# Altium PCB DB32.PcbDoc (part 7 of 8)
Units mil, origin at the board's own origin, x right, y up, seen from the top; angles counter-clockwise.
Board outline 3236.22 x 4456.69 mil, 8 copper layers (Top Layer, MidLayer1, MidLayer2, GND-Layer5, MidLayer3, VCC, MidLayer4, Bottom Layer), stack 61.8 mil thick; 207 components, 474 nets, 1777 pads, 1474 vias.
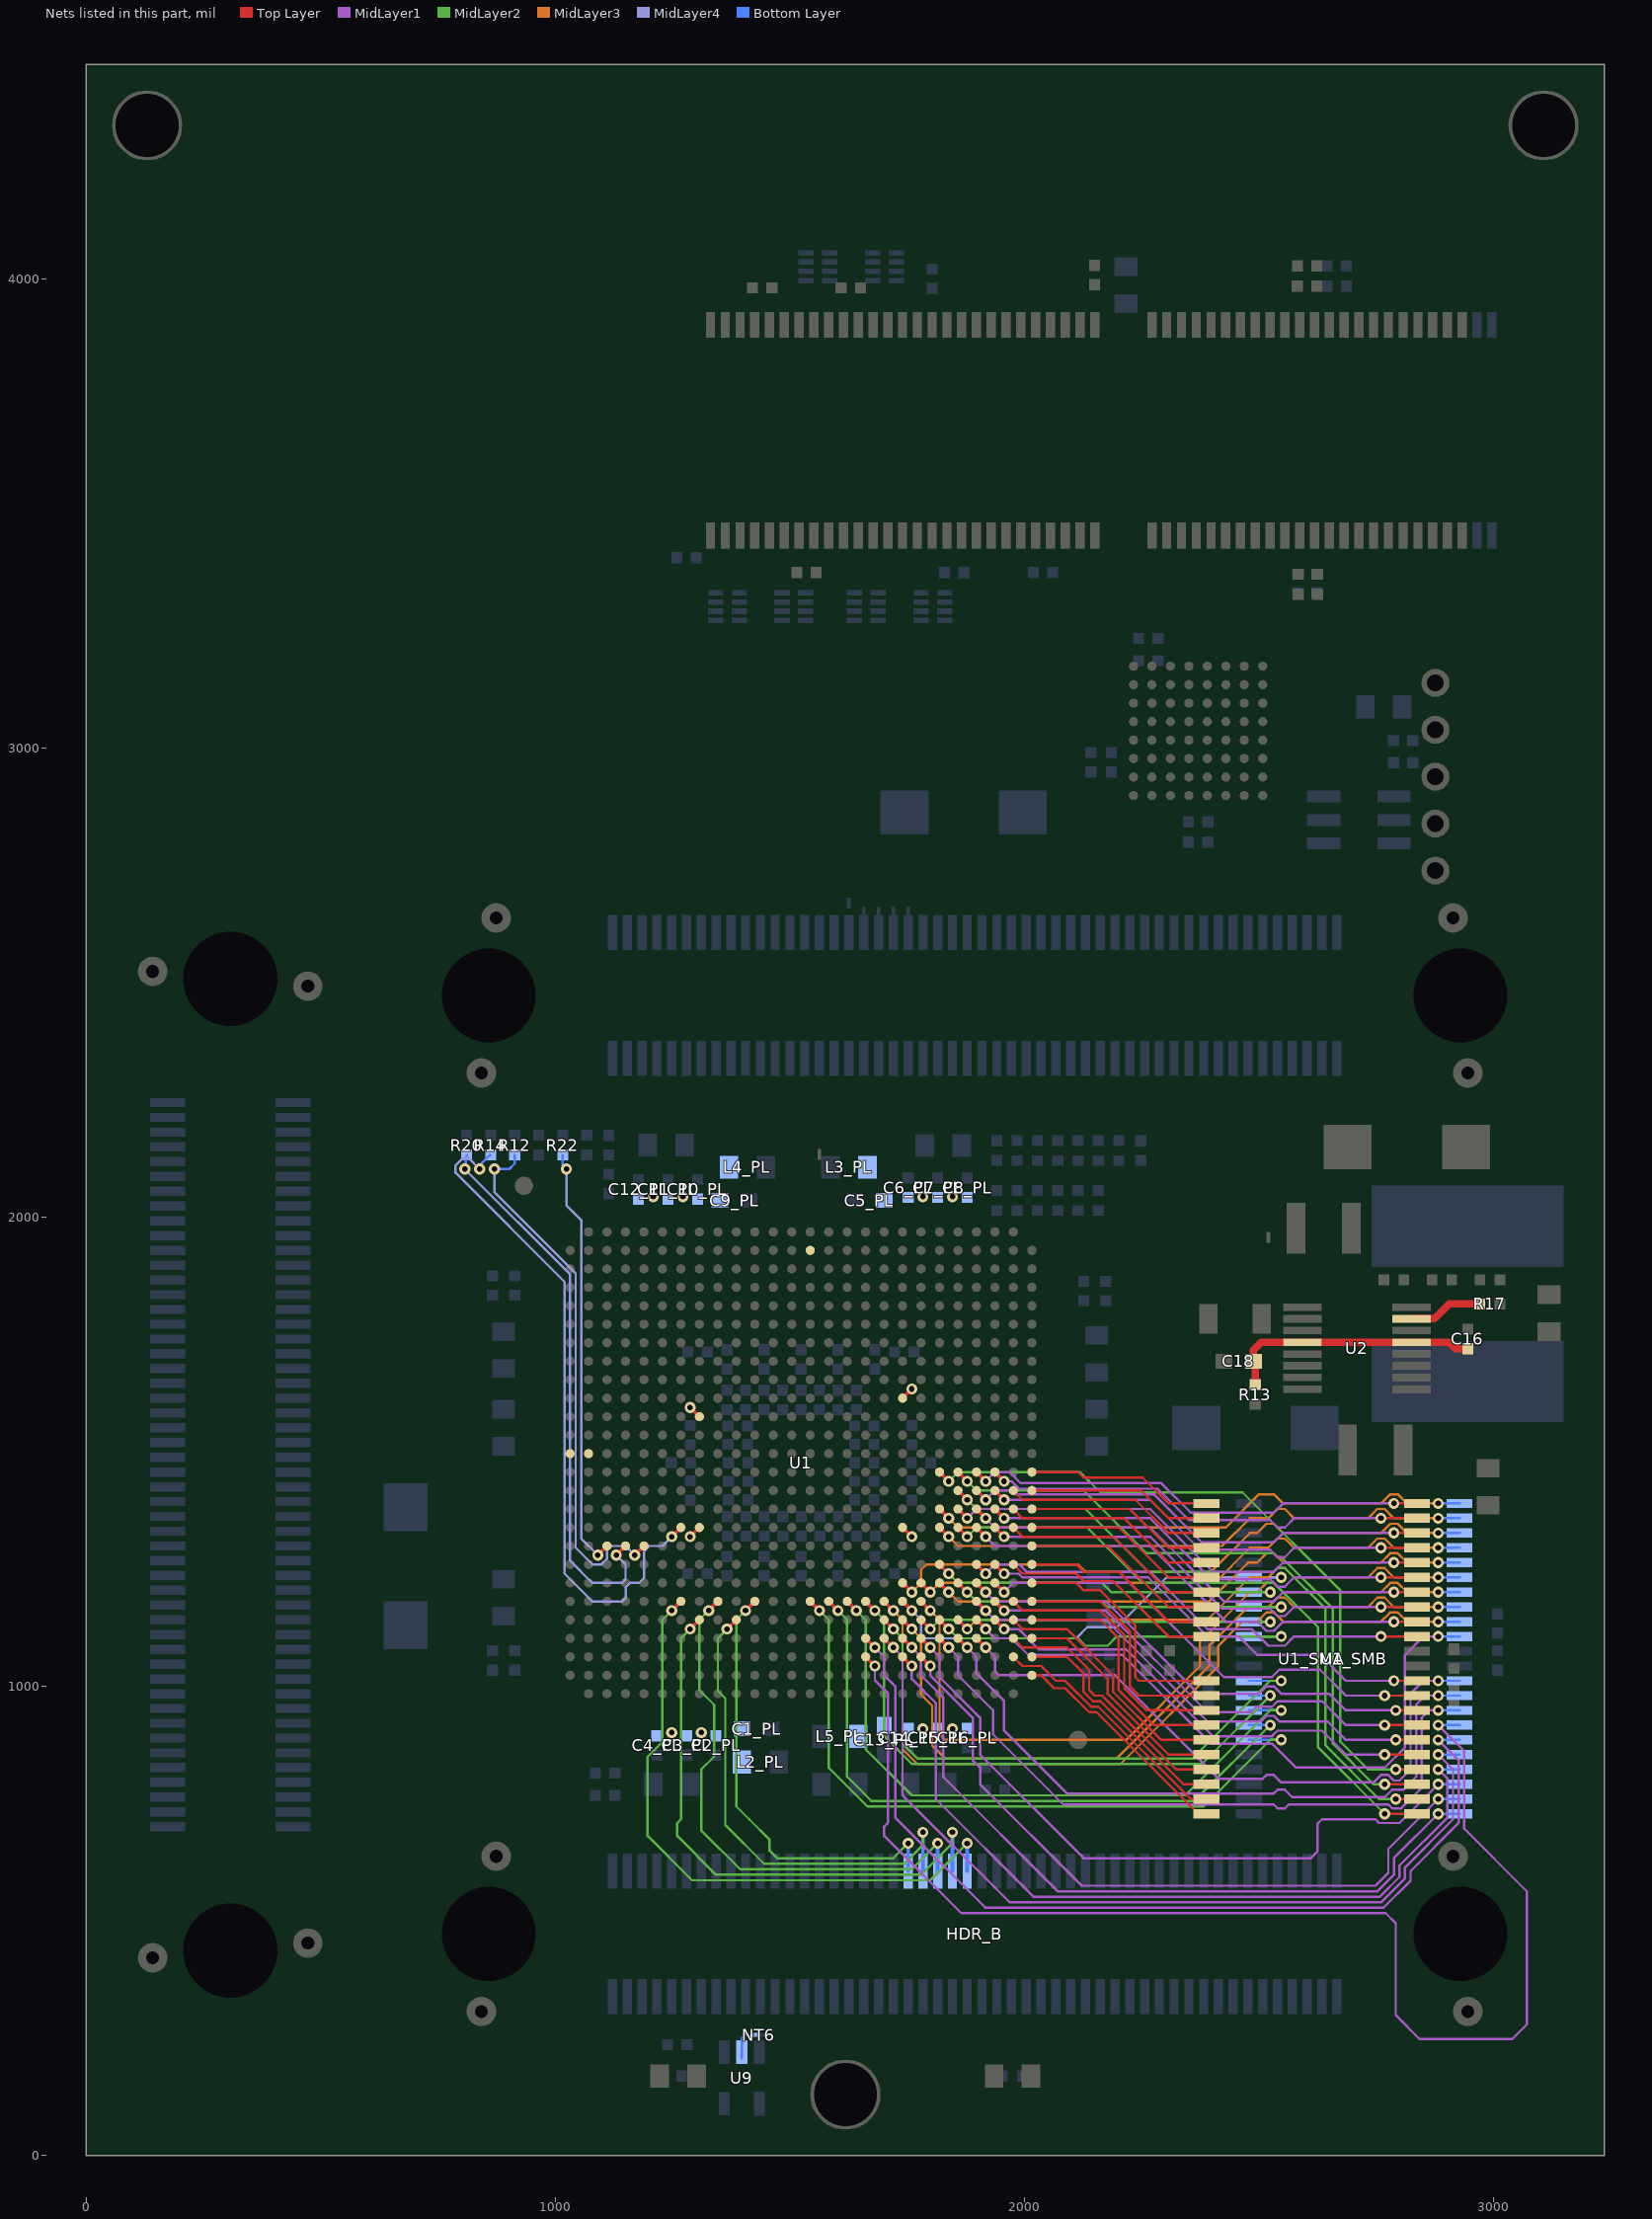
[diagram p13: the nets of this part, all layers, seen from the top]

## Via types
v1: diameter 23.62, hole 11.81, Top Layer to Bottom Layer, 839 vias
v2: diameter 23.62, hole 11.81, Top Layer to Bottom Layer, tented both sides, 499 vias
v3: diameter 27.56, hole 15.75, Top Layer to Bottom Layer, 135 vias
v4: diameter 23.62, hole 11.81, Top Layer to Bottom Layer, tented top, 1 vias

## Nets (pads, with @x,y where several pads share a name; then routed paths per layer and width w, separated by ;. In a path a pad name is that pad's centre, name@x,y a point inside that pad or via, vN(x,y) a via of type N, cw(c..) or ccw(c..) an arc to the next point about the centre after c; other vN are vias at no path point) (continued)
SRAM1_A10: U1.T21 U1_SMB.23 | length 1178.5
  Top Layer w7.87: U1.T21@1818.9,1377.95 v1(1838.59,1358.27)
  MidLayer3 w5: v1(1838.59,1358.27) 1858.27,1338.58 2078.74,1338.58 2090.55,1338.58 2429.16,1338.58 2500.01,1409.44 2531.7,1409.44 2551.38,1389.76 2759.84,1389.76 2779.53,1409.45 2795.28,1409.45 2814.97,1389.75 v1(2881.9,1389.75)
  Bottom Layer w5: v1(2881.9,1389.75) U1_SMB.23@2927.25,1389.75
SRAM1_A11: U1.U21 U1_SMB.24 | length 1181.8
  Top Layer w7.87: U1.U21@1818.9,1338.58 v1(1838.59,1318.9)
  MidLayer3 w5: v1(1838.59,1318.9) 1858.27,1299.21 2078.74,1299.21 2090.55,1299.21 2421.26,1299.21 2480.31,1358.27 2519.69,1358.27 2539.37,1377.95 2555.12,1377.95 2574.8,1358.27 2732.28,1358.27 2751.97,1377.95 2767.72,1377.95 2787.41,1358.26 v1(2881.9,1358.26)
  Bottom Layer w5: v1(2881.9,1358.26) U1_SMB.24@2927.25,1358.26
SRAM1_A12: U1.Y19 U1_SMB.25 | length 1309.2
  Top Layer w7.87: U1.Y19@1740.16,1220.47 v1(1759.84,1200.79)
  MidLayer3 w5: v1(1759.84,1200.79) 1779.53,1220.47 1779.53,1248.03 1791.34,1259.84 2078.74,1259.84 2090.55,1259.84 2114.17,1259.84 2129.92,1244.09 2397.66,1244.09 2480.33,1326.76 2496.27,1326.76 2515.96,1346.45 2531.7,1346.45 2551.38,1326.77 2759.84,1326.77 2779.53,1346.46 2795.28,1346.46 2814.97,1326.76 v1(2881.9,1326.76)
  Bottom Layer w5: v1(2881.9,1326.76) U1_SMB.25@2927.25,1326.76
SRAM1_A13: U1.Y20 U1_SMB.26 | length 1227.6
  Top Layer w7.87: U1.Y20@1779.53,1220.47 v1(1799.21,1200.79)
  MidLayer3 w5: v1(1799.21,1200.79) 1818.9,1220.47 2078.74,1220.47 2090.55,1220.47 2405.51,1220.47 2480.31,1295.28 2519.69,1295.28 2539.37,1314.96 2555.12,1314.96 2574.8,1295.28 2732.28,1295.28 2751.97,1314.96 2767.72,1314.96 2787.41,1295.27 v1(2881.9,1295.27)
  Bottom Layer w5: v1(2881.9,1295.27) U1_SMB.26@2927.25,1295.27
SRAM1_A14: U1.Y21 U1_SMB.27 | length 1191.5
  Top Layer w7.87: U1.Y21@1818.9,1220.47 v1(1838.58,1200.79)
  MidLayer3 w5: v1(1838.58,1200.79) 1858.27,1181.1 2078.74,1181.1 2090.55,1181.1 2393.7,1181.1 2476.37,1263.77 2496.27,1263.77 2515.96,1283.45 2531.7,1283.45 2551.38,1263.78 2759.84,1263.78 2779.53,1283.46 2795.28,1283.46 2814.97,1263.77 v1(2881.9,1263.77)
  Bottom Layer w5: v1(2881.9,1263.77) U1_SMB.27@2927.25,1263.77
SRAM1_A15: U1.AC20 U1_SMB.42 | length 1519.6
  Top Layer w7.87: U1.AC20@1779.53,1102.36 v1(1799.21,1082.68)
  MidLayer1 w5: v1(1799.21,1082.68) 1818.9,1062.99 1818.9,1019.69 1905.51,933.07 1905.51,921.26 1905.51,909.45 1905.51,854.33 2125.98,633.86 2610.24,633.86 2624.26,647.88 2624.26,706.94 2633.86,716.54 2748.03,716.54 2755.91,708.66 2799.21,708.66 v1(2881.9,791.33)
  Bottom Layer w5: v1(2881.9,791.33) U1_SMB.42@2927.25,791.33
SRAM1_A16: U1.AD20 U1_SMB.43 | length 1541.7
  Top Layer w7.87: U1.AD20@1779.53,1062.99 v1(1799.21,1043.31)
  MidLayer1 w5: v1(1799.21,1043.31) 1799.21,1023.62 1889.76,933.07 1889.76,921.26 1889.76,909.45 1889.76,842.52 1905.51,826.77 1905.51,791.34 2121.8,575.05 2748.28,575.05 2775.59,602.36 2775.59,653.54 v1(2881.9,759.83)
  Bottom Layer w5: v1(2881.9,759.83) U1_SMB.43@2927.25,759.83
SRAM1_A17: U1.AC19 U1_SMB.44 | length 1621.8
  Top Layer w7.87: U1.AC19@1740.16,1102.36 v1(1759.84,1082.68)
  MidLayer1 w5: v1(1759.84,1082.68) 1779.53,1062.99 1779.53,1023.62 1826.77,976.38 1826.77,921.26 1826.77,911.26 1826.77,807.09 2070.62,563.24 2752.21,563.24 2787.4,598.43 2787.4,633.86 v1(2881.9,728.34)
  Bottom Layer w5: v1(2881.9,728.34) U1_SMB.44@2927.25,728.34
SRAM1_A18: U1.AB22 U1_SMB.28 | length 1155.4
  Top Layer w7.87: U1.AB22@1858.27,1141.73 v1(1877.95,1122.05)
  MidLayer3 w5: v1(1877.95,1122.05) 1897.64,1141.73 2078.74,1141.73 2090.55,1141.73 2389.76,1141.73 2480.31,1232.28 2519.69,1232.28 2539.37,1251.97 2555.12,1251.97 2574.8,1232.28 2732.28,1232.28 2751.97,1251.97 2767.72,1251.97 2787.41,1232.28 v1(2881.9,1232.27)
  Bottom Layer w5: v1(2881.9,1232.27) U1_SMB.28@2927.25,1232.27
SRAM1_D0: U1.AA15 U1_SMB.7 | length 1429.5
  Top Layer w7.87: U1.AA15@1582.68,1181.1 v1(1602.36,1161.42)
  MidLayer2 w5: v1(1602.36,1161.42) 1622.05,1141.73 1622.05,921.26 1622.05,909.45 1622.05,807.09 1673.23,755.91 2362.2,755.91 2523.6,917.3 v1(2523.83,917.3)
  Bottom Layer w5: U1_SMB.7@2478.43,917.32 v1(2523.83,917.3) v1@2527.77,917.3
SRAM1_D1: U1.AA16 U1_SMB.8 | length 1405.6
  Top Layer w7.87: U1.AA16@1622.05,1181.1 v1(1641.73,1161.42)
  MidLayer2 w5: v1(1641.73,1161.42) 1661.42,1141.73 1661.42,921.26 1661.42,909.45 1661.42,866.14 1759.84,767.72 2342.52,767.72 2523.62,948.82 v1(2547.24,948.82)
  Bottom Layer w5: U1_SMB.8@2478.43,948.82 v1(2547.24,948.82) v1@2551.18,948.82
SRAM1_D2: U1.AA17 U1_SMB.9 | length 1261.1
  Top Layer w7.87: U1.AA17@1661.42,1181.1 v1(1681.1,1161.42)
  MidLayer2 w5: v1(1681.1,1161.42) 1700.79,1141.73 1700.79,921.26 1700.79,909.45 1700.79,893.7 1759.84,834.65 2378.17,834.65 v1(2523.83,980.31) v1@2523.61,980.31
  Bottom Layer w5: U1_SMB.9@2478.43,980.32 v1(2523.83,980.31) v1@2527.77,980.31
SRAM1_D3: U1.AB18 U1_SMB.10 | length 1241.5
  Top Layer w7.87: U1.AB18@1700.79,1141.73 v1(1720.47,1122.05)
  MidLayer2 w5: v1(1720.47,1122.05) 1740.16,1102.36 1740.16,921.26 1740.16,909.45 1740.16,877.95 1771.65,846.46 2358.27,846.46 2523.62,1011.81 v1(2547.24,1011.81)
  Bottom Layer w5: U1_SMB.10@2478.43,1011.81 v1(2547.24,1011.81) v1@2551.18,1011.81
SRAM1_D4: U1.AB21 U1_SMB.13 | length 832.1
  Top Layer w7.87: U1.AB21@1818.9,1141.73 v1(1838.58,1122.05)
  MidLayer2 w5: v1(1838.58,1122.05) 1858.27,1102.36 2078.74,1102.36 2090.55,1102.36 2114.17,1102.36 2129.92,1086.61 2177.17,1086.61 2196.85,1106.3 v1(2547.24,1106.3)
  Bottom Layer w5: U1_SMB.13@2478.43,1106.3 v1(2547.24,1106.3) v1@2551.18,1106.3
SRAM1_D5: U1.AB20 U1_SMB.14 | length 811.6
  Top Layer w7.87: U1.AB20@1779.53,1141.73 v1(1799.21,1122.05)
  MidLayer2 w5: v1(1799.21,1122.05) 1818.9,1141.73 2078.74,1141.73 2090.55,1141.73 2169.28,1141.73 2173.23,1137.79 v1(2523.83,1137.79)
  Bottom Layer w5: U1_SMB.14@2478.43,1137.8 v1(2523.83,1137.79) v1@2527.77,1137.79
SRAM1_D6: U1.Y22 U1_SMB.15 | length 782.9
  Top Layer w7.87: U1.Y22@1858.27,1220.47 v1(1877.95,1200.79)
  MidLayer2 w5: v1(1877.95,1200.79) 1897.64,1181.1 2078.74,1181.1 2090.55,1181.1 2165.35,1181.1 2177.17,1169.29 v1(2547.24,1169.29)
  Bottom Layer w5: U1_SMB.15@2478.43,1169.29 v1(2547.24,1169.29) v1@2551.18,1169.29
SRAM1_D7: U1.W21 U1_SMB.16 | length 778.7
  Top Layer w7.87: U1.W21@1818.9,1259.84 v1(1838.59,1240.16)
  MidLayer2 w5: v1(1838.59,1240.16) 1858.27,1220.47 2078.74,1220.47 2090.55,1220.47 2165.35,1220.47 2185.04,1200.79 v1@2523.83,1200.79
  Bottom Layer w5: U1_SMB.16@2478.44,1200.78 v1(2523.83,1200.78) v1@2527.77,1200.78
SRAM1_D8: U1.AA20 U1_SMB.29 | length 1606.1
  Top Layer w7.87: U1.AA20@1779.53,1181.1 v1(1799.21,1161.42)
  MidLayer3 w5: v1(1799.21,1161.42) 1818.9,1141.73 1818.9,921.26 1818.9,909.45 1818.9,897.64 1830.71,885.83 2216.54,885.83 2374.02,1043.31 2374.02,1094.49 2480.3,1200.78 2496.27,1200.78 2515.96,1220.46 2531.7,1220.46 2551.38,1200.79 2759.84,1200.79 2779.53,1220.47 2795.28,1220.47 2814.97,1200.78 v1(2881.9,1200.78)
  Bottom Layer w5: v1(2881.9,1200.78) U1_SMB.29@2927.25,1200.78
SRAM1_D9: U1.AB19 U1_SMB.30 | length 1621
  Top Layer w7.87: U1.AB19@1740.16,1141.73 v1(1759.84,1122.05)
  MidLayer3 w5: v1(1759.84,1122.05) 1779.53,1102.36 1779.53,982.28 1803.15,958.66 1803.15,921.26 1803.15,909.45 1803.15,874.02 1830.71,846.46 2196.85,846.46 2393.7,1043.31 2393.7,1086.61 2476.38,1169.29 2519.69,1169.29 2539.37,1188.98 2555.12,1188.98 2574.8,1169.29 2732.28,1169.29 2751.97,1188.98 2767.72,1188.98 2787.41,1169.29 v1(2881.9,1169.28)
  Bottom Layer w5: v1(2881.9,1169.28) U1_SMB.30@2927.25,1169.28
SRAM1_D10: U1.AA18 U1_SMB.31 | length 1715
  Top Layer w7.87: U1.AA18@1700.79,1181.1 v1(1720.47,1161.42)
  MidLayer3 w5: v1(1720.47,1161.42) 1740.16,1141.73 1740.16,921.26 1740.16,909.45 1740.16,866.14 1771.65,834.65 2204.72,834.65 2413.39,1043.31 2413.39,1086.61 2464.56,1137.79 2496.27,1137.79 2515.96,1157.47 2531.7,1157.47 2551.38,1137.8 2759.84,1137.8 2779.53,1157.48 2795.28,1157.48 2814.97,1137.79 v1(2881.9,1137.79)
  Bottom Layer w5: v1(2881.9,1137.79) U1_SMB.31@2927.25,1137.79
SRAM1_D11: U1.AB23 U1_SMB.32 | length 1395.5
  Top Layer w7.87: U1.AB23@1897.64,1141.73 v1(1917.32,1122.05)
  MidLayer1 w5: v1(1917.32,1122.05) 1937.01,1102.36 1972.44,1102.36 2007.88,1066.93 2078.74,1066.93 2090.55,1066.93 2208.66,1066.93 2397.64,877.95 2527.56,877.95 2578.75,826.76 2767.71,826.76 2811.02,870.08 2811.02,1066.93 2850.39,1106.3 2862.59,1106.3 ; 2858.28,1106.29 v1(2881.9,1106.29)
  Bottom Layer w5: v1(2881.9,1106.29) U1_SMB.32@2927.25,1106.29
SRAM1_D12: U1.AC23 U1_SMB.35 | length 1403.6
  Top Layer w7.87: U1.AC23@1897.64,1102.36 v1(1917.33,1082.68)
  MidLayer1 w5: 2862.21,1011.8 v1(2881.9,1011.8) ; 2862.2,1011.81 2850.39,1011.81 2822.83,984.25 2822.83,822.83 2799.21,799.21 2787.4,799.21 2775.6,811.02 2759.84,811.02 2744.09,795.27 2547.24,795.27 2531.5,811.02 2515.75,811.02 2507.87,803.15 2413.39,803.15 2192.91,1023.62 2090.55,1023.62 2078.74,1023.62 1944.88,1023.62 1937.01,1031.5 1937.01,1062.99 ; 1937.01,1062.99 v1(1917.33,1082.68) 1937.01,1062.99
  Bottom Layer w5: v1(2881.9,1011.8) U1_SMB.35@2927.25,1011.8
SRAM1_D13: U1.AC22 U1_SMB.36 | length 1453
  Top Layer w7.87: U1.AC22@1858.27,1102.36 v1(1877.96,1082.68)
  MidLayer1 w5: v1(1877.96,1082.68) 1897.64,1062.99 1897.64,1027.56 1956.69,968.5 1956.69,921.26 1956.69,909.45 1956.69,905.51 2090.55,771.65 2531.5,771.65 2539.37,779.53 2555.12,779.53 2570.87,763.78 2767.71,763.77 2783.46,779.52 2807.08,779.52 2834.65,807.09 2834.65,960.63 2854.33,980.32 2862.2,980.32 v1(2881.9,980.31)
  Bottom Layer w5: v1(2881.9,980.31) U1_SMB.36@2927.25,980.31
SRAM1_D14: U1.AC21 U1_SMB.37 | length 1492
  Top Layer w7.87: U1.AC21@1818.9,1102.36 v1(1838.59,1082.68)
  MidLayer1 w5: v1(1838.59,1082.68) 1858.27,1062.99 1858.27,1023.62 1933.07,948.82 1933.07,921.26 1933.07,909.45 1933.07,897.64 2082.68,748.03 2531.5,748.03 2539.37,740.16 2555.12,740.16 2562.99,748.03 2775.59,748.03 2783.46,740.16 2803.15,740.16 2846.46,783.46 2846.46,933.07 2862.2,948.82 v1(2881.9,948.81)
  Bottom Layer w5: v1(2881.9,948.81) U1_SMB.37@2927.25,948.81
SRAM1_D15: U1.AD17 U1_SMB.38 | length 2843.4
  Top Layer w7.87: U1.AD17@1661.42,1062.99 v1(1681.1,1043.3)
  MidLayer1 w5: v1(1681.1,1043.3) 1681.1,1012.79 1708.66,985.23 1708.66,921.26 1708.66,909.45 1708.66,708.66 1700.79,700.79 1700.79,681.1 1865.16,516.73 2769.68,516.73 2791.34,495.08 2791.34,299.21 2842.52,248.03 3039.37,248.03 3070.87,279.53 3070.87,562.99 2937.01,696.85 2937.01,862.2 v1(2881.9,917.31)
  Bottom Layer w5: v1(2881.9,917.31) U1_SMB.38@2927.25,917.31
SRAM1_NBHE: U1.AC18 U1_SMB.40 | length 1901.6
  Top Layer w7.87: U1.AC18@1700.79,1102.36 v1(1720.47,1082.68)
  MidLayer1 w5: v1(1720.47,1082.68) 1740.16,1062.99 1740.16,921.26 1740.16,909.45 1740.16,767.72 1967.77,540.11 2760.58,540.11 2811.02,590.55 2811.02,614.17 2913.39,716.54 2913.39,822.83 v1(2881.9,854.32)
  Bottom Layer w5: v1(2881.9,854.32) U1_SMB.40@2927.25,854.32
SRAM1_NBLE: U1.AC17 U1_SMB.39 | length 2015.4
  Top Layer w7.87: U1.AC17@1661.42,1102.36 v1(1681.1,1082.68)
  MidLayer1 w5: v1(1681.1,1082.68) 1700.79,1062.99 1700.79,1023.62 1724.41,1000 1724.41,921.26 1724.41,909.45 1724.41,720.47 1916.34,528.54 2765.75,528.54 2822.83,585.63 2822.83,606.3 2925.2,708.66 2925.2,842.52 v1(2881.9,885.82)
  Bottom Layer w5: v1(2881.9,885.82) U1_SMB.39@2927.25,885.82
SRAM1_NCS: U1.AA14 U1_SMB.6 | length 1500.9
  Top Layer w7.87: U1.AA14@1543.31,1181.1 v1(1562.99,1161.42)
  MidLayer2 w5: v1(1562.99,1161.42) 1582.68,1141.73 1582.68,921.26 1582.68,909.45 1582.68,826.77 1665.35,744.09 2381.89,744.09 2523.62,885.83 v1(2547.24,885.83)
  Bottom Layer w5: U1_SMB.6@2478.43,885.83 v1(2547.24,885.83) v1@2551.18,885.83
SRAM1_NOE: U1.AD19 U1_SMB.41 | length 1749.5
  Top Layer w7.87: U1.AD19@1740.16,1062.99 v1(1759.84,1043.31)
  MidLayer1 w5: v1(1759.84,1043.31) 1759.84,1015.75 1811.02,964.57 1811.02,921.26 1811.02,909.45 1811.02,759.84 2019.19,551.67 2757.38,551.67 2799.21,593.5 2799.21,618.11 2901.57,720.47 2901.57,803.15 v1(2881.9,822.83)
  Bottom Layer w5: v1(2881.9,822.83) U1_SMB.41@2927.25,822.83
SRAM1_NWE: U1.AA19 U1_SMB.17 | length 984.7
  Top Layer w7.87: U1.AA19@1740.16,1181.1 v1(1759.84,1161.42)
  MidLayer4 w5: v1(1759.84,1161.42) 1779.53,1141.73 1779.53,1110.24 1787.4,1102.36 2078.74,1102.36 2090.55,1102.36 2110.24,1102.36 2133.86,1125.98 2196.85,1125.98 2303.15,1232.28 v1(2547.24,1232.28)
  Bottom Layer w5: U1_SMB.17@2478.43,1232.28 v1(2547.24,1232.28) v1@2551.18,1232.28
SRAM2_A0: U1.U22 U1_SMA.1 | length 1397.4
  Top Layer w5: v1(2767.69,728.34) U1_SMA.1@2836.69,728.35
  Top Layer w7.87: U1.U22@1858.27,1338.58 v1(1877.96,1318.9)
  MidLayer2 w5: v1(1877.96,1318.9) 1897.64,1338.58 2078.74,1338.58 2090.55,1338.58 2133.86,1338.58 2251.97,1220.47 2531.5,1220.47 2625.98,1125.98 2625.98,870.08 v1(2767.69,728.34)
SRAM2_A1: U1.R22 U1_SMA.2 | length 1428
  Top Layer w5: v1(2791.34,759.84) U1_SMA.2@2836.69,759.84
  Top Layer w7.87: U1.R22@1858.27,1417.32 v1(1877.96,1397.64)
  MidLayer2 w5: v1(1877.96,1397.64) 1897.64,1377.95 2078.74,1377.95 2090.55,1377.95 2129.92,1377.95 2263.78,1244.09 2531.5,1244.09 2539.37,1251.97 2555.12,1251.97 2641.73,1165.35 2641.73,874.02 2755.91,759.84 v1(2791.34,759.84)
SRAM2_A2: U1.P22 U1_SMA.3 | length 1422.4
  Top Layer w5: v1(2767.69,791.34) U1_SMA.3@2836.69,791.34
  Top Layer w7.87: U1.P22@1858.27,1456.69 v1(1877.96,1437.01)
  MidLayer2 w5: v1(1877.96,1437.01) 1897.64,1417.32 2078.74,1417.32 2090.55,1417.32 2125.98,1417.32 2259.84,1283.46 2531.5,1283.46 2539.37,1275.59 2547.24,1275.59 2657.48,1165.35 2657.48,877.95 2744.1,791.34 v1(2767.69,791.34)
SRAM2_A3: U1.P21 U1_SMA.4 | length 1485.8
  Top Layer w5: v1(2791.34,822.83) U1_SMA.4@2836.69,822.84
  Top Layer w7.87: U1.P21@1818.9,1456.69 v1(1838.59,1437.01)
  MidLayer2 w5: v1(1838.59,1437.01) 1858.27,1456.69 2078.74,1456.69 2090.55,1456.69 2118.11,1456.69 2161.42,1413.39 2464.57,1413.39 2673.23,1204.72 2673.23,881.89 2732.28,822.83 v1(2791.34,822.83)
SRAM2_A4: U1.AB24 U1_SMA.5 | length 1020.7
  Top Layer w5: v1(2767.69,854.33) U1_SMA.5@2836.69,854.33
  Top Layer w7.87: U1.AB24@1937.01,1141.73 v1(1956.69,1122.05)
  MidLayer1 w5: v1(1956.69,1122.05) 1987.21,1122.05 2030.51,1078.74 2078.74,1078.74 2090.55,1078.74 2216.54,1078.74 2401.57,893.7 2527.56,893.7 2539.37,905.51 2633.86,905.51 2685.04,854.33 v1@2759.84,854.31
SRAM2_A5: U1.T22 U1_SMA.18 | length 1058.4
  Top Layer w5: v1@2787.4,1263.77 U1_SMA.18@2836.71,1263.77
  Top Layer w7.87: U1.T22@1858.27,1377.95 v1(1877.96,1358.27)
  MidLayer1 w5: v1(1877.96,1358.27) 1897.64,1377.95 2078.74,1377.95 2090.55,1377.95 2267.72,1377.95 2401.57,1244.09 2531.5,1244.09 2551.18,1263.78 v1(2787.4,1263.78)
SRAM2_A6: U1.R24 U1_SMA.19 | length 966.6
  Top Layer w5: v1(2759.84,1295.28) U1_SMA.19@2836.69,1295.28
  Top Layer w7.87: U1.R24@1937.01,1417.32 v1(1956.7,1397.64)
  MidLayer1 w5: v1(1956.7,1397.64) 2078.74,1397.64 2090.55,1397.64 2267.72,1397.64 2374.02,1291.34 2523.62,1291.34 2539.37,1275.59 2555.12,1275.59 2574.8,1295.28 v1(2759.84,1295.28)
SRAM2_A7: U1.R23 U1_SMA.20 | length 1009.2
  Top Layer w5: v1(2787.4,1326.77) U1_SMA.20@2836.69,1326.77
  Top Layer w7.87: U1.R23@1897.64,1417.32 v1(1917.33,1397.64)
  MidLayer1 w5: v1(1917.33,1397.64) 1937.01,1417.32 1972.44,1417.32 1980.32,1409.45 2078.74,1409.45 2090.55,1409.45 2275.59,1409.45 2377.95,1307.09 2531.5,1307.09 2551.18,1326.77 v1(2787.4,1326.77)
SRAM2_A8: U1.P24 U1_SMA.21 | length 956.8
  Top Layer w5: v1(2759.84,1358.27) U1_SMA.21@2836.69,1358.27
  Top Layer w7.87: U1.P24@1937.01,1456.69 v1(1956.7,1437.01)
  MidLayer1 w5: v1(1956.7,1437.01) 1972.44,1437.01 1988.19,1421.26 2078.74,1421.26 2090.55,1421.26 2283.46,1421.26 2350.39,1354.33 2523.62,1354.33 2539.37,1338.58 2555.12,1338.58 2574.8,1358.27 v1(2759.84,1358.27)
SRAM2_A9: U1.P23 U1_SMA.22 | length 999.4
  Top Layer w5: v1(2787.4,1389.76) U1_SMA.22@2836.69,1389.76
  Top Layer w7.87: U1.P23@1897.64,1456.69 v1(1917.33,1437.01)
  MidLayer1 w5: v1(1917.33,1437.01) 1937.01,1456.69 1968.5,1456.69 1992.13,1433.07 2078.74,1433.07 2090.55,1433.07 2291.34,1433.07 2354.33,1370.08 2531.5,1370.08 2551.18,1389.76 v1(2787.4,1389.76)
SRAM2_A10: U1.P26 U1_SMA.23 | length 399.9
  Top Layer w5: U1.P26@2015.75,1456.69 2078.74,1456.69 2090.55,1456.69 2114.17,1456.69 2125.98,1444.88 2251.97,1444.88 2307.1,1389.76 U1_SMA.23@2387.87,1389.76
SRAM2_A11: U1.R26 U1_SMA.24 | length 396.6
  Top Layer w5: U1.R26@2015.75,1417.32 2078.74,1417.32 2090.55,1417.32 2248.03,1417.32 2307.09,1358.26 U1_SMA.24@2387.87,1358.27
SRAM2_A12: U1.R25 U1_SMA.25 | length 449
  Top Layer w5: U1.R25@1976.38,1417.32 1996.06,1397.64 2078.74,1397.64 2090.55,1397.64 2236.22,1397.64 2307.09,1326.76 U1_SMA.25@2387.87,1326.77
SRAM2_A13: U1.T26 U1_SMA.26 | length 406.4
  Top Layer w5: U1.T26@2015.75,1377.95 2078.74,1377.95 2090.55,1377.95 2224.41,1377.95 2307.09,1295.27 U1_SMA.26@2387.87,1295.28
SRAM2_A14: U1.T25 U1_SMA.27 | length 458.8
  Top Layer w5: U1.T25@1976.38,1377.95 1996.06,1358.27 2078.74,1358.27 2090.55,1358.27 2212.6,1358.27 2307.09,1263.77 U1_SMA.27@2387.89,1263.77
SRAM2_A15: U1.AD26 U1_SMA.42 | length 507.7
  Top Layer w5: U1.AD26@2015.75,1062.99 2078.74,1062.99 2090.55,1062.99 2125.98,1027.56 2125.98,988.19 2145.67,968.5 2161.42,968.5 2338.59,791.33 U1_SMA.42@2387.87,791.34
SRAM2_A16: U1.AD25 U1_SMA.43 | length 537.1
  Top Layer w5: U1.AD25@1976.38,1062.99 1996.06,1043.31 2035.43,1043.31 2066.93,1011.81 2078.74,1011.81 2086.61,1011.81 2141.73,956.69 2157.48,956.69 2354.34,759.83 U1_SMA.43@2387.87,759.84
SRAM2_A17: U1.AE26 U1_SMA.44 | length 494.5
  Top Layer w5: U1.AE26@2015.75,1023.62 2035.43,1023.62 2062.99,996.06 2078.74,996.06 2086.61,996.06 2137.8,944.88 2153.54,944.88 2370.09,728.34 U1_SMA.44@2387.87,728.35
SRAM2_A18: U1.U26 U1_SMA.28 | length 416.2
  Top Layer w5: U1.U26@2015.75,1338.58 2078.74,1338.58 2090.55,1338.58 2200.79,1338.58 2307.09,1232.28 U1_SMA.28@2387.89,1232.28
SRAM2_D0: U1.AA24 U1_SMA.7 | length 1020.9
  Top Layer w5: v1(2767.69,917.32) U1_SMA.7@2836.69,917.32
  Top Layer w7.87: U1.AA24@1937.01,1181.1 v1(1956.7,1161.42)
  MidLayer1 w5: v1(1956.7,1161.42) 2078.74,1161.42 2090.55,1161.42 2173.23,1161.42 2389.76,944.88 2482.35,944.88 2494.16,956.69 2527.58,956.69 2539.11,968.23 2539.11,968.5 2633.86,968.5 2685.06,917.3 v1@2759.84,917.3
SRAM2_D1: U1.Y23 U1_SMA.8 | length 1060.7
  Top Layer w5: v1(2791.34,948.82) U1_SMA.8@2836.69,948.82
  Top Layer w7.87: U1.Y23@1897.64,1220.47 v1(1917.32,1200.79)
  MidLayer1 w5: v1(1917.32,1200.79) 1937.01,1181.1 2078.74,1181.1 2090.55,1181.1 2173.23,1181.1 2370.08,984.25 2500,984.25 2515.75,1000 2531.5,1000 2547.24,984.25 2649.61,984.25 2685.04,948.83 v1@2787.41,948.83
SRAM2_D2: U1.Y24 U1_SMA.9 | length 1020.7
  Top Layer w5: v1(2767.69,980.31) U1_SMA.9@2836.69,980.32
  Top Layer w7.87: U1.Y24@1937.01,1220.47 v1(1956.69,1200.79)
  MidLayer1 w5: v1(1956.69,1200.79) 1976.38,1220.47 2078.74,1220.47 2090.55,1220.47 2224.41,1220.47 2425.2,1019.68 2527.56,1019.68 2543.31,1035.43 2629.92,1035.43 2685.04,980.32 ; 2685.04,980.29 v1@2759.84,980.29
SRAM2_D3: U1.W24 U1_SMA.10 | length 1002.4
  Top Layer w5: v1(2787.4,1011.81) U1_SMA.10@2836.69,1011.81
  Top Layer w7.87: U1.W24@1937.01,1259.84 v1(1956.7,1240.16)
  MidLayer1 w5: v1(1956.7,1240.16) 1987.21,1240.16 1995.08,1232.28 2078.74,1232.28 2090.55,1232.28 2263.78,1232.28 2389.76,1106.3 2456.69,1106.3 2496.06,1066.93 2629.92,1066.93 2685.03,1011.82 v1(2787.4,1011.81)
SRAM2_D4: U1.W23 U1_SMA.13 | length 1035.3
  Top Layer w5: v1(2759.84,1106.3) U1_SMA.13@2836.69,1106.3
  Top Layer w7.87: U1.W23@1897.64,1259.84 v1(1917.33,1240.16)
  MidLayer1 w5: v1(1917.33,1240.16) 1937.01,1259.84 1988.19,1259.84 2003.94,1244.09 2078.74,1244.09 2090.55,1244.09 2267.72,1244.09 2389.76,1122.05 2484.25,1122.05 2519.68,1086.62 2555.11,1086.62 2574.79,1106.31 v1(2759.84,1106.3)
SRAM2_D5: U1.U23 U1_SMA.14 | length 1038.6
  Top Layer w5: v1(2787.4,1137.8) U1_SMA.14@2836.69,1137.8
  Top Layer w7.87: U1.U23@1897.64,1338.58 v1(1917.33,1318.9)
  MidLayer1 w5: v1(1917.33,1318.9) 1937.01,1299.21 2078.74,1299.21 2090.55,1299.21 2267.72,1299.21 2429.13,1137.8 2496.06,1137.8 2515.75,1118.11 2531.49,1118.11 2551.17,1137.8 ; 2551.17,1137.8 v1(2787.4,1137.8)
SRAM2_D6: U1.U24 U1_SMA.15 | length 986.1
  Top Layer w5: v1(2759.84,1169.29) U1_SMA.15@2836.69,1169.29
  Top Layer w7.87: U1.U24@1937.01,1338.58 v1(1956.7,1318.9)
  MidLayer1 w5: v1(1956.7,1318.9) 2078.74,1318.9 2090.55,1318.9 2267.72,1318.9 2421.25,1165.36 2523.61,1165.36 2539.36,1149.61 2555.11,1149.61 2574.79,1169.3 v1(2759.84,1169.29)
SRAM2_D7: U1.T23 U1_SMA.16 | length 1028.8
  Top Layer w5: v1(2787.4,1200.79) U1_SMA.16@2836.69,1200.79
  Top Layer w7.87: U1.T23@1897.64,1377.95 v1(1917.33,1358.27)
  MidLayer1 w5: v1(1917.33,1358.27) 1937.01,1338.58 2078.74,1338.58 2090.55,1338.58 2267.72,1338.58 2425.2,1181.1 2531.49,1181.1 ; 2531.49,1181.11 2551.17,1200.8 ; 2551.17,1200.8 v1(2787.4,1200.79)
SRAM2_D8: U1.U25 U1_SMA.29 | length 468.6
  Top Layer w5: U1.U25@1976.38,1338.58 1996.06,1318.9 2078.74,1318.9 2090.55,1318.9 2188.98,1318.9 2307.09,1200.78 U1_SMA.29@2387.87,1200.79
SRAM2_D9: U1.V26 U1_SMA.30 | length 426
  Top Layer w5: U1.V26@2015.75,1299.21 2078.74,1299.21 2090.55,1299.21 2177.17,1299.21 2307.09,1169.28 U1_SMA.30@2387.87,1169.29
SRAM2_D10: U1.W26 U1_SMA.31 | length 422.7
  Top Layer w5: U1.W26@2015.75,1259.84 2078.74,1259.84 2090.55,1259.84 2110.24,1259.84 2125.98,1244.09 2200.79,1244.09 2307.09,1137.79 U1_SMA.31@2387.87,1137.8
SRAM2_D11: U1.W25 U1_SMA.32 | length 475.1
  Top Layer w5: U1.W25@1976.38,1259.84 1996.06,1240.16 2078.74,1240.16 2090.55,1240.16 2110.24,1240.16 2125.98,1224.41 2188.98,1224.41 2307.09,1106.29 U1_SMA.32@2387.87,1106.3
SRAM2_D12: U1.Y26 U1_SMA.35 | length 523.1
  Top Layer w5: U1.Y26@2015.75,1220.47 2078.74,1220.47 2090.55,1220.47 2110.24,1220.47 2125.98,1204.72 2161.42,1204.72 2236.22,1129.92 2236.22,1019.68 2244.1,1011.8 U1_SMA.35@2387.87,1011.81
SRAM2_D13: U1.AA26 U1_SMA.36 | length 524.5
  Top Layer w5: U1.AA26@2015.75,1181.1 2078.74,1181.1 2090.55,1181.1 2161.42,1181.1 2224.41,1118.11 2224.41,1000 2244.1,980.31 U1_SMA.36@2387.87,980.32
SRAM2_D14: U1.AA25 U1_SMA.37 | length 574.6
  Top Layer w5: U1.AA25@1976.38,1181.1 1996.06,1161.42 2078.74,1161.42 2090.55,1161.42 2161.42,1161.42 2212.6,1110.24 2212.6,996.06 2259.85,948.81 U1_SMA.37@2387.87,948.82
SRAM2_D15: U1.AB26 U1_SMA.38 | length 529.7
  Top Layer w5: U1.AB26@2015.75,1141.73 2078.74,1141.73 2090.55,1141.73 2161.42,1141.73 2200.79,1102.36 2200.79,992.13 2275.6,917.32 U1_SMA.38@2387.87,917.32
SRAM2_NBHE: U1.AC26 U1_SMA.40 | length 493.3
  Top Layer w5: U1.AC26@2015.75,1102.36 2078.74,1102.36 2090.55,1102.36 2177.17,1015.75 2177.17,984.25 2307.09,854.32 U1_SMA.40@2387.87,854.33
SRAM2_NBLE: U1.AB25 U1_SMA.39 | length 538.3
  Top Layer w5: U1.AB25@1976.38,1141.73 1996.06,1122.05 2078.74,1122.05 2090.55,1122.05 2188.98,1023.62 2188.98,988.19 2291.35,885.82 U1_SMA.39@2387.87,885.83
SRAM2_NCS: U1.AA23 U1_SMA.6 | length 1067.2
  Top Layer w5: v1(2791.34,885.83) U1_SMA.6@2836.69,885.83
  Top Layer w7.87: U1.AA23@1897.64,1181.1 v1(1917.33,1161.42)
  MidLayer1 w5: v1(1917.33,1161.42) 1937.01,1141.73 1976.38,1141.73 2078.74,1141.73 2090.55,1141.73 2173.23,1141.73 2389.76,925.2 2503.93,925.2 2515.75,937.01 2531.5,937.01 2543.31,925.2 2645.67,925.2 2685.03,885.83 v1@2787.41,885.83
SRAM2_NOE: U1.AC25 U1_SMA.41 | length 552.7
  Top Layer w5: U1.AC25@1976.38,1102.36 1996.06,1082.68 2078.74,1082.68 2090.55,1082.68 2137.8,1035.43 2137.8,992.13 2149.61,980.32 2165.35,980.32 2322.84,822.83 U1_SMA.41@2387.87,822.84
SRAM2_NWE: U1.T24 U1_SMA.17 | length 976.3
  Top Layer w5: v1(2759.84,1232.28) U1_SMA.17@2836.71,1232.28
  Top Layer w7.87: U1.T24@1937.01,1377.95 v1(1956.7,1358.27)
  MidLayer1 w5: v1(1956.7,1358.27) 2078.74,1358.27 2090.55,1358.27 2267.72,1358.27 2397.63,1228.35 2523.61,1228.35 2539.36,1212.61 2555.11,1212.61 2574.79,1232.29 v1(2759.84,1232.28)
STATUS_LED: NT6.1 U9.2 | length 70.8
  Bottom Layer w5: U9.2@1397.64,207.68 1397.64,250.22 1404.53,257.11 NT6.1@1423,257.11
SW0: HDR_B.42 U1.AA11 | length 951.1
  Top Layer w7.87: v1(1405.51,1161.42) U1.AA11@1425.2,1181.1
  MidLayer2 w5: v1(1405.51,1161.42) 1385.83,1141.73 1385.83,921.26 1385.83,909.45 1385.83,744.09 1413.39,716.54 1456.69,673.23 1456.69,649.61 1472.44,633.86 1720.47,633.86 v2(1751.97,665.35)
  Bottom Layer w7.87: HDR_B.42@1751.97,606.3 v2(1751.97,665.35)
SW1: HDR_B.44 U1.AB10 | length 1041.9
  Top Layer w7.87: v1(1366.14,1122.05) U1.AB10@1385.83,1141.73
  MidLayer2 w5: v1(1366.14,1122.05) 1346.46,1102.36 1346.46,990.15 1362.2,974.41 1362.2,921.26 1362.2,909.45 1362.2,704.72 1444.88,622.05 1744.09,622.05 1783.46,661.42 v2(1783.46,688.98)
  Bottom Layer w7.87: HDR_B.44@1783.47,606.3 v2(1783.46,688.98)
SW2: HDR_B.46 U1.AA9 | length 1149
  Top Layer w7.87: v1(1326.77,1161.42) U1.AA9@1346.46,1181.1
  MidLayer2 w5: v1(1326.77,1161.42) 1307.09,1141.73 1307.09,1086.61 1307.09,992.12 1338.58,960.63 1338.58,921.26 1338.58,909.45 1338.58,850.39 1311.02,822.83 1311.02,692.91 1393.7,610.24 1759.84,610.24 v2(1814.96,665.35)
  Bottom Layer w7.87: HDR_B.46@1814.96,606.3 v2(1814.96,665.35)
SW3: HDR_B.48 U1.AB8 | length 1235.1
  Top Layer w7.87: v1(1287.4,1122.05) U1.AB8@1307.09,1141.73
  MidLayer2 w5: v1(1287.4,1122.05) 1267.72,1102.36 1267.72,921.26 1267.72,909.45 1267.72,716.54 1259.84,708.66 1259.84,681.1 1342.52,598.43 1779.53,598.43 1846.46,665.35 v2(1846.46,688.98)
  Bottom Layer w7.87: HDR_B.48@1846.46,606.3 v2(1846.46,688.98)
SW4: HDR_B.50 U1.AA7 | length 1341.3
  Top Layer w7.87: v1(1248.03,1161.42) U1.AA7@1267.72,1181.1
  MidLayer2 w5: v1(1248.03,1161.42) 1228.35,1141.73 1228.35,921.26 1228.35,909.45 1228.35,881.89 1196.85,850.39 1196.85,681.1 1291.34,586.61 1799.21,586.61 v2(1877.95,665.35)
  Bottom Layer w7.87: HDR_B.50@1877.96,606.3 v2(1877.95,665.35)
TCK: R14.2 U1.U7 | length 1458.2
  Top Layer w7.87: v1(1248.03,1318.9) U1.U7@1267.72,1338.58
  MidLayer4 w5: v1(838.58,2102.36) 814.96,2125.98 803.15,2125.98 787.4,2110.24 787.4,2094.49 1019.68,1862.2 1019.68,1240.16 1078.74,1181.1 1141.98,1181.1 1149.81,1188.93 1149.81,1211.08 1159.4,1220.67 1178.65,1220.67 1188.98,1231 1188.98,1287.4 1200.79,1299.21 1228.35,1299.21 v1(1248.03,1318.9)
  Bottom Layer w5: v1(838.58,2102.36) 838.58,2110.24 860.7,2132.36 R14.2@862.2,2132.36
TDI: R20.2 U1.V4 | length 1186
  Top Layer w7.87: v1(1129.92,1279.53) U1.V4@1149.61,1299.21
  MidLayer4 w5: v1(807.09,2102.36) 1031.5,1877.95 1031.5,1267.72 1078.74,1220.47 1141.73,1220.47 1149.61,1228.35 1149.61,1259.84 v1(1129.92,1279.53)
  Bottom Layer w5: v1(807.09,2102.36) R20.2@811.02,2132.36
TDO: R22.2 U1.V3 | length 911.7
  Top Layer w7.87: v1(1090.55,1279.53) U1.V3@1110.24,1299.21
  MidLayer4 w5: v1(1023.62,2102.36) 1023.62,2025.05 1055.12,1993.55 1055.12,1314.96 v1(1090.55,1279.53)
  Bottom Layer w5: R22.2@1015.75,2132.36 1015.74,2110.24 v1(1023.62,2102.36)
TMS: R12.2 U1.V5 | length 1149.7
  Top Layer w7.87: v1(1169.29,1279.53) U1.V5@1188.98,1299.21
  MidLayer4 w5: v1(870.08,2102.36) 870.08,2053.51 1043.31,1880.28 1043.31,1295.28 1078.74,1259.84 1098.43,1259.84 1110.24,1271.65 1110.24,1291.34 1118.11,1299.21 1149.6,1299.21 v1(1169.29,1279.53)
  Bottom Layer w5: v1(870.08,2102.36) 901.57,2102.36 913.38,2114.17 R12.2@913.38,2132.36
TOFF: R17.1 U2.7 | length 159.5
  Top Layer w15.75: U2.7@2824.58,1783.25 2824.8,1783.46 2874.02,1783.46 2905.51,1814.96 R17.1@2970.94,1814.96
UGCLK0: U1.B14
UGCLK1: U1.N1
UGCLK2: U1.N2
VCCA_PLL1: C1_PL.1 C2_PL.1 C3_PL.1 C4_PL.1 L2_PL.2 U1.U8 | length 27.8
  Top Layer w7.87: v1(1287.4,1318.9) U1.U8@1307.09,1338.58
  other v1: 1248.03,901.57 1311.02,901.57
VCCA_PLL2: C5_PL.1 C6_PL.1 C7_PL.1 C8_PL.1 L3_PL.2 U1.K19 | length 27.8
  Top Layer w7.87: U1.K19@1740.16,1614.17 v1(1759.84,1633.86)
  other v1: 1783.46,2043.31 1846.46,2043.31
VCCA_PLL3: C9_PL.1 C10_PL.1 C11_PL.1 C12_PL.1 L4_PL.2 U1.L8 | length 27.8
  Top Layer w7.87: v1(1287.4,1594.49) U1.L8@1307.09,1574.8
  other v1: 1208.66,2043.31 1271.65,2043.31
VCCA_PLL4: C13_PL.1 C14_PL.1 C15_PL.1 C16_PL.1 L5_PL.2 U1.U19 | length 27.8
  Top Layer w7.87: U1.U19@1740.16,1338.58 v1(1759.84,1318.9)
  other v1: 1783.46,909.45 1846.46,909.45
VFILT: C16.1 C18.1 R13.2 U2.5 U2.12 | length 544.3
  Top Layer w15.75: R13.2@2492.12,1643.23 2492.12,1688.98 C18.1@2488.18,1692.91 2488.19,1716.54 2504.9,1733.25 U2.12@2592.58,1733.25 ; U2.12@2592.58,1733.25 U2.5@2824.58,1733.25 2904.53,1733.27 2918.31,1719.48 C16.1@2944.88,1719.48
pads on no net: HDR_B.93 HDR_B.95 HDR_B.MH5 HDR_B.MH6 HDR_L.MH5 HDR_L.MH6 HDR_T.95 HDR_T.MH5 HDR_T.MH6 MH1.MOUNT MH2.MOUNT MH3.MOUNT U1.A7 U1.A8 U1.A12 U1.A13 U1.A17 U1.A18 U1.AA13 U1.AB3 U1.AB14 U1.AC5 U1.AC9 U1.AC15 U1.AD4 U1.AD5 U1.AD14 U1.AE13 U1.AE25 U1.B6 U1.B8 U1.B13 U1.B17 U1.B18 U1.B19 U1.B22 U1.B23 U1.B24 U1.C7 U1.C9 U1.C13 U1.C18 U1.D4 U1.D7 U1.D9 U1.E4 U1.E6 U1.E7 U1.E8 U1.E9 U1.E11 U1.E17 U1.E21 U1.F5 U1.F7 U1.F8 U1.F19 U1.FID1 U1.G5 U1.G7 U1.G10 U1.H5 U1.H6 U1.J5 U1.J6 U1.J7 U1.K5 U1.K6 U1.K25 U1.L5 U1.L6 U1.L7 U1.L22 U1.L25 U1.L26 U1.M1 U1.M6 U1.M23 U1.M24 U1.M25 U1.M26 U1.N4 U1.N5 U1.N6 U1.N21 U1.N24 U1.N25 U1.N26 U1.P2 U1.P5 U1.P25 U1.V6 U1_CM.A1 U1_CM.A8 U1_CM.B1 U1_CM.B4 U1_CM.C1 U1_CM.D1 U1_CM.E1 U1_CM.F8 U1_CM.G1 U1_CM.G8 U1_CM.H1 U1_CM.H8 U1_ID.5 U2_CM.40 U3_CM.40 U9.1
copper on no net: | length 8826
  Top Layer w5: 1208.66,2019.68 1208.66,1948.82 1228.35,1929.14 ; 1267.72,1968.51 1267.72,1980.32 1291.34,2003.94 1291.34,2031.5 ; 1307.09,1929.14 1287.4,1948.82 1287.4,1980.31 1307.09,2000 1307.09,2031.5 ; 1307.09,1968.5 1307.09,1984.25 1322.83,2000 1322.83,2031.5 ; 1464.57,1968.5 1464.57,1984.25 1472.44,1992.12 1472.44,2031.5 ; 1523.62,933.07 1523.62,1043.31 1543.31,1062.99 ; 1661.42,1929.13 1681.1,1948.82 1681.1,1984.25 1677.17,1988.19 1677.17,2031.5 ; 1661.42,1968.5 1661.42,2031.5 ; 1692.91,2031.5 1692.91,1992.13 1700.79,1984.25 1700.79,1968.5 ; 1700.79,1929.13 1720.47,1948.82 1720.47,1984.25 1708.66,1996.06 1708.66,2031.5 ; 1740.16,1929.14 1759.84,1948.82 1759.84,1980.31 1740.16,2000 1740.16,2031.5 ; 1858.27,1929.14 1877.95,1948.82 1877.95,2031.5 ; 1897.64,1929.14 1917.32,1948.82 1917.32,2031.5 ; 1937.01,1496.06 1956.69,1476.38 2078.74,1476.38 ; 1937.01,1929.14 1956.69,1948.82 1956.69,2031.49 ; 1976.37,1023.63 2031.5,968.5 2078.74,968.5 ; 1976.38,1535.43 1996.06,1555.12 2078.74,1555.12 ; 1976.38,1574.8 1996.06,1594.49 2078.74,1594.49 ; 1976.38,1614.17 1996.06,1633.86 2078.74,1633.86 ; 2015.75,1496.06 2078.74,1496.06 ; 2015.75,1535.43 2078.74,1535.43 ; 2015.75,1574.8 2078.74,1574.8
  Top Layer w7.87: v1(1129.92,1043.31) 1149.61,1062.99 ; v1(1129.92,1830.71) 1149.61,1811.02 ; v1(1129.92,1870.08) 1149.61,1850.39 ; v1(1169.29,1043.31) 1188.98,1062.99 ; v1(1169.29,1082.68) 1188.98,1102.36 ; v1(1169.29,1594.49) 1188.98,1574.8 ; v1(1169.29,1633.86) 1188.98,1614.17 ; v1(1169.29,1673.23) 1188.98,1653.54 ; v1(1169.29,1712.6) 1188.98,1692.91 ; v1(1169.29,1751.97) 1188.98,1732.28 ; v1(1169.29,1791.34) 1188.98,1771.65 ; v1(1208.66,1279.53) 1228.35,1299.21 ; v1(1208.66,1515.75) 1228.35,1496.06 ; v1(1208.66,1555.12) 1228.35,1535.43 ; v1(1208.66,1594.49) 1228.35,1574.8 ; v1(1208.66,1633.86) 1228.35,1614.17 ; v1(1208.66,1673.23) 1228.35,1653.54 ; v1(1208.66,1712.6) 1228.35,1692.91 ; v1(1208.66,1830.71) 1228.35,1811.02 ; v1(1248.03,1594.49) 1267.72,1574.8 ; v1(1248.03,1673.23) 1267.72,1653.54 ; v1(1248.03,1751.97) 1267.72,1732.28 ; v1(1248.03,1791.34) 1267.72,1771.65 ; v1(1248.03,1830.71) 1267.72,1811.02 ; v1(1248.03,1870.08) 1267.72,1850.39 ; v1(1248.03,1909.45) 1267.72,1889.76 ; v1(1287.4,1791.34) 1307.09,1771.65 ; v1(1287.4,1830.71) 1307.09,1811.02 ; v1(1326.77,1082.68) 1346.46,1102.36 ; v1(1326.77,1830.71) 1346.46,1811.02 ; v1(1326.77,1870.08) 1346.46,1850.39 ; v1(1326.77,1909.45) 1346.46,1889.76 ; v1(1366.14,1751.97) 1385.83,1732.28 ; v1(1405.51,1830.71) 1425.2,1811.02 ; v1(1484.25,1161.42) 1503.94,1181.1 ; v1(1484.25,1909.45) 1503.94,1889.76 ; 1582.67,1102.37 v1(1602.36,1082.68) ; 1661.42,1811.02 v1(1681.1,1830.71) ; 1700.79,1889.76 v1(1720.47,1909.45) ; 1740.16,1771.65 v1(1759.84,1791.34) ; 1818.9,1811.02 v1(1838.58,1830.71) ; 1858.27,1574.8 v1(1877.96,1594.49) ; 1897.64,1535.43 v1(1917.33,1555.12) ; 1937.01,1535.43 v1(1956.7,1555.12) ; 3149.61,4212.6 3149.61,4330.71 ; v1(1090.55,1122.05) 1110.24,1141.73 v1(1090.55,1122.05)
  MidLayer1 w5: 1153.54,921.26 1153.54,1023.62 1149.61,1027.56 1149.61,1062.99 v1(1169.29,1082.68) ; 1240.16,2031.5 1240.16,1940.95 1248.03,1933.07 v1(1248.03,1909.45) ; 1307.09,921.26 1307.09,1062.99 v1(1326.77,1082.68) ; 1311.02,2031.5 1311.02,1948.82 1307.09,1944.88 1307.09,1889.76 v1(1326.77,1870.08) ; v1(1326.77,1909.45) 1326.77,2031.49 ; 1582.68,921.26 1582.68,1062.99 v1(1602.36,1082.68) ; 968.51,1122.04 v1(1090.55,1122.05) 968.51,1122.05
  MidLayer2 w5: 968.5,1574.8 1188.98,1574.8 v1(1208.66,1594.49) ; 968.5,1614.17 1188.98,1614.17 v1(1208.66,1633.86) ; 968.51,1653.54 1149.61,1653.54 v1(1169.29,1633.86) ; 968.51,1692.91 1149.61,1692.91 v1(1169.29,1673.23) ; 968.51,1732.29 1188.97,1732.29 v1(1208.66,1712.6) ; 968.51,1771.65 1149.61,1771.65 v1(1169.29,1751.97) ; 1024.32,1850.71 1185.86,1850.71 1205.86,1830.71 v1(1208.66,1830.71) ; 1050.04,1810.85 1257.59,1810.85 1267.92,1821.18 1267.92,1848.01 1248.03,1867.9 v1(1248.03,1870.08) ; v1(1129.92,1870.08) 1149.44,1889.6 1149.44,1947.41 ; 1189.3,1921.94 1189.3,1861.41 1200,1850.71 1228.03,1850.71 v1(1248.03,1830.71) ; 1244.09,2031.5 1244.09,1964.57 1267.72,1940.94 1267.72,1889.76 1267.72,1862.35 1287.4,1842.67 v1(1287.4,1830.71) ; 1456.69,921.26 1456.69,976.38 1464.57,984.26 1464.57,1086.61 1464.57,1141.73 v1(1484.25,1161.42)
  MidLayer3 w5: 968.5,1259.84 1188.97,1259.84 v1(1208.66,1279.53) ; 1078.2,1653.24 1188.67,1653.24 v1(1208.66,1673.23) ; 1081.89,1692.74 1219.56,1692.74 1228.05,1684.25 1228.05,1665.07 1208.66,1645.68 v1(1208.66,1633.86) ; 1082.26,1613.8 1216.09,1613.8 1228.52,1626.23 1228.52,1641.9 1248.03,1661.41 v1(1248.03,1673.23) ; v1(1208.66,1712.6) v1@1214.41,1712.6
  MidLayer4 w5: v1(1405.51,1830.71) 1425.2,1850.39 1425.2,2031.5 ; v1(1484.25,1909.45) 1484.25,2031.5 ; 1661.42,2031.5 1661.42,1850.39 v1(1681.1,1830.71) ; v1(1877.96,1594.49) 1897.64,1574.8 2078.74,1574.8
  other v1: 1618.11,43.31 1456.69,59.06 1771.65,59.06 1556.86,68.68 1679.36,68.68 1531.5,129.92 1704.72,129.92 1556.86,191.17 1679.36,191.17 1618.11,216.54 129.92,4240.16 3106.3,4240.16 68.68,4265.53 191.17,4265.53 3045.05,4265.53 3167.54,4265.53 43.31,4326.77 216.54,4326.77 3019.68,4326.77 3192.91,4326.77 68.68,4388.02 191.17,4388.02 3045.05,4388.02 3167.54,4388.02 129.92,4413.39 3106.3,4413.39

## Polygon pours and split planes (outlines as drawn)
GND on Top Layer "GROUND-TOP-LAYER" (solid, remove dead copper, pour order 1015): 19.68,4132.62 298.72,4132.62 298.72,4409.45 2929.63,4409.45 2929.63,4132.62 3208.66,4132.62 3208.66,19.68 1813.48,19.68 1813.48,296.52 1414.86,296.52 1414.86,19.68 19.68,19.68
AGND on Top Layer "AGND-TOP" (solid, remove dead copper, pour order 1014): 2377.61,2077.57 2377.61,1677.17 3088.3,1677.17 3088.3,2077.57
GND on MidLayer1 "GROUND-MID1-LAYER" (solid, remove dead copper, pour order 1016): 19.68,4132.62 298.72,4132.62 298.72,4409.45 2929.63,4409.45 2929.63,4132.62 3208.66,4132.62 3208.66,19.68 1813.48,19.68 1813.48,296.52 1414.86,296.52 1414.86,19.68 19.68,19.68
1V2 on MidLayer1 "FPGAPWR-ML1-1V2" (solid, pour order 1012): 1472.36,1857.68 1472.36,2031.21 1575.03,2031.21 1575.03,1854.05 1811.25,1854.05 1901.81,1763.5 1901.81,1523.34 2078.97,1523.34 2078.97,1424.91 1901.81,1424.91 1901.81,1188.69 1811.25,1098.14 1575.03,1098.14 1575.03,920.98 1472.67,920.98 1472.67,1098.14 1236.45,1098.14 1145.9,1188.69 1145.9,1424.91 968.74,1424.91 968.74,1527.28 1145.9,1527.28 1145.9,1771.37 1228.58,1854.05
1V2 on MidLayer1 "1V2-connect-to-L1-C17" (solid, remove dead copper, pour order 1013): 1988.19,1417.32 3157.48,1417.32 3157.48,2244.09 2442.91,2244.09 2442.91,1706.69 1988.19,1706.69
GND on MidLayer2 "GROUND-MID2-LAYER" (solid, remove dead copper, pour order 1017): 19.68,4132.62 298.72,4132.62 298.72,4409.45 2929.63,4409.45 2929.63,4132.62 3208.66,4132.62 3208.66,19.68 1813.48,19.68 1813.48,296.52 1414.86,296.52 1414.86,19.68 19.68,19.68
GND on MidLayer3 "GROUND-MID3-LAYER" (solid, remove dead copper, pour order 1018): 19.68,4132.62 298.72,4132.62 298.72,4409.45 2929.63,4409.45 2929.63,4132.62 3208.66,4132.62 3208.66,19.68 1813.48,19.68 1813.48,296.52 1414.86,296.52 1414.86,19.68 19.68,19.68
VCCA_PLL1 on MidLayer3 "VCCA_PLL1_MID3" (solid, remove dead copper, pour order 1009): 1330.71,881.89 1224.41,881.89 1224.41,1334.65 1224.41,1334.64 1311.02,1334.64 1311.02,948.82 1330.71,948.82
VCCA_PLL3 on MidLayer3 "VCCA_PLL3_MID3" (solid, remove dead copper, pour order 1011): 1385.36,1575.4 1185.04,1574.8 1185.04,2059.06 1385.83,2059.03
GND on MidLayer4 "GROUND-MID4-LAYER" (solid, remove dead copper, pour order 1019): 19.68,4132.62 298.72,4132.62 298.72,4409.45 2929.63,4409.45 2929.63,4132.62 3208.66,4132.62 3208.66,19.68 1813.48,19.68 1813.48,296.52 1414.86,296.52 1414.86,19.68 19.68,19.68
VCCA_PLL4 on MidLayer4 "VCCA_PLL4_MID4" (solid, remove dead copper, pour order 1000): 1862.2,893.7 1862.2,1334.65 1728.96,1334.65 1728.96,1213.64 1710.75,1213.64 1696.85,1200 1697.65,1199.21 1697.65,1050 1722.34,1050 1733,1039.54 1733,893.7
VCCA_PLL2 on MidLayer4 "VCCA_PLL2_MID4" (solid, remove dead copper, pour order 1010): 1696.85,2062.99 1866.14,2062.99 1866.14,2019.68 1783.46,2019.68 1783.46,1618.11 1696.85,1618.11
GND on Bottom Layer "GROUND-BOTTOM-LAYER" (solid, remove dead copper, pour order 1020): 19.68,4132.62 298.72,4132.62 298.72,4409.45 2929.63,4409.45 2929.63,4132.62 3208.66,4132.62 3208.66,19.68 1813.48,19.68 1813.48,296.52 1414.86,296.52 1414.86,19.68 19.68,19.68
VCCA_PLL1 on Bottom Layer "VCCA_PLL1_BL" (solid, remove dead copper, pour order 1005): 1429.13,803.15 1429.13,933.07 1192.91,933.07 1192.91,881.89 1366.14,881.89 1366.14,803.15
VCCA_PLL2 on Bottom Layer "VCCA_PLL2_BL" (solid, remove dead copper, pour order 1006): 1657.48,2145.67 1714.47,2145.67 1714.47,2062.99 1897.64,2062.99 1897.64,2019.68 1665.62,2019.68 1665.62,2055.12 1657.48,2055.12
VCCA_PLL3 on Bottom Layer "VCCA_PLL3_BL" (solid, remove dead copper, pour order 1007): 1389.76,2157.5 1334.65,2157.5 1334.65,2064.48 1157.48,2064.48 1157.48,2015.75 1381.89,2015.75 1381.89,2055.62 1389.76,2055.62
VCCA_PLL4 on Bottom Layer "VCCA_PLL4_BL" (solid, remove dead copper, pour order 1008): 1901.57,932.67 1901.57,884.98 1666.7,884.98 1666.7,850.3 1618.11,850.3 1618.11,937.01 1901.57,937.01
GND on Bottom Layer "FPGAPWR-BL-GND" (solid, remove dead copper, pour order 1001): 1397.64,1602.36 1649.61,1602.36 1649.61,1350.39 1397.64,1350.39
1V2 on Bottom Layer "1V2-BL" (solid, remove dead copper, pour order 1004): 1433.07,2240.16 1433.07,2059.06 1602.36,2059.06 1602.36,2149.61 2559.06,2149.61 2559.06,2066.93 3070.87,2066.93 3070.87,2240.16
3V3 on Bottom Layer "FPGAPWR-BL-3V3" (solid, pour order 1002): 1303.15,1704.72 1303.15,1259.84 1746.76,1259.84 1746.76,1704.72
1V2 on Bottom Layer "FPGAPWR-BL-1V2" (solid, pour order 1003): 1083.33,1956.69 1979.86,1956.69 2003.88,1932.68 2003.88,1020.08 1979.86,996.06 1067.32,996.06 1043.31,1020.08 1043.31,1932.68 1067.32,1956.69
GND on GND-Layer5 (split plane): 3216.12,4436.6 3216.12,20.1 20.1,20.1 20.1,4436.6 1523.62,4436.6
3V3 on VCC (split plane): 1523.62,4436.6 2701.84,4436.6 2701.84,4061.24 2702.17,4058.67 2703.17,4056.27 2704.74,4054.22 2720.98,4037.98 2721.87,4037.3 2723.04,4036.4 2725.43,4035.41 2728,4035.07 3041.89,4035.07 3106.07,3970.89 3106.07,2319.11 3064.6,2277.64 2921.43,2277.64 2802.3,2396.78 2800.24,2398.36 2797.84,2399.35 2795.28,2399.69 2629.92,2399.69 2627.35,2399.35 2624.96,2398.36 2622.9,2396.78 2617,2390.88 2615.42,2388.82 2614.43,2386.43 2614.09,2383.86 2614.09,2206.87 2429.99,2022.77 2428.41,2020.71 2427.42,2018.32 2427.08,2015.75 2427.08,1590.55 2427.42,1587.98 2428.41,1585.59 2429.99,1583.53 2445.74,1567.78 2447.79,1566.21 2450.19,1565.21 2452.76,1564.88 2582.68,1564.88 2585.25,1565.21 2587.64,1566.21 2589.7,1567.78 2618.29,1596.37 2712.19,1596.37 2725.07,1583.49 2725.07,1440 2725.41,1437.43 2726.4,1435.04 2727.98,1432.98 2732.98,1427.98 2735.04,1426.4 2737.43,1425.41 2740,1425.07 3005.77,1425.07 3045.19,1385.65 3045.19,1287.4 3045.19,1244.09 3045.19,795.45 2948.64,698.9 2838.58,698.9 2836.01,698.57 2833.62,697.57 2831.56,696 2780.38,644.82 2778.8,642.76 2777.81,640.36 2777.47,637.8 2777.47,523.8 2617,363.32 2615.42,361.26 2614.43,358.87 2614.09,356.3 2614.09,20.1 20.1,20.1 20.1,4436.6 1523.62,4436.6
5V0 on VCC (split plane): 3216.12,4436.6 3216.12,20.1 2633.94,20.1 2633.94,352.19 2794.42,512.67 2796,514.72 2796.99,517.12 2797.33,519.68 2797.33,633.68 2842.69,679.05 2952.76,679.05 2955.33,679.39 2957.72,680.38 2959.78,681.96 3062.14,784.32 3063.03,785.48 3063.72,786.37 3064.01,787.08 3064.71,788.77 3065.05,791.34 3065.05,1244.09 3065.05,1287.4 3065.05,1389.76 3064.71,1392.33 3063.72,1394.73 3062.82,1395.89 3062.14,1396.78 3016.9,1442.02 3014.85,1443.6 3012.45,1444.59 3009.88,1444.93 2744.93,1444.93 2744.93,1587.6 2744.59,1590.17 2743.6,1592.56 2742.02,1594.62 2723.32,1613.32 2721.26,1614.9 2718.87,1615.89 2716.3,1616.23 2614.17,1616.23 2611.6,1615.89 2609.21,1614.9 2607.15,1613.32 2578.57,1584.73 2456.87,1584.73 2446.94,1594.66 2446.94,2011.64 2631.04,2195.74 2632.61,2197.79 2633.6,2200.19 2633.94,2202.76 2633.94,2379.75 2634.03,2379.84 2791.16,2379.84 2910.3,2260.7 2911.2,2260.01 2912.36,2259.12 2914.75,2258.13 2917.32,2257.79 3068.72,2257.79 3071.29,2258.13 3073.68,2259.12 3075.74,2260.7 3123.02,2307.98 3124.6,2310.04 3125.59,2312.43 3125.93,2315 3125.93,3975 3125.59,3977.57 3124.6,3979.96 3123.7,3981.13 3123.02,3982.02 3053.02,4052.02 3050.96,4053.6 3048.57,4054.59 3046,4054.93 2732.11,4054.93 2721.69,4065.35 2721.69,4436.6

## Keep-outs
Bottom Layer:
  rectangle: 1310.91,4194.61 1507.76,4289.09
  rectangle: 255.91,3149.61 452.76,3244.09
  rectangle: 2643.7,3334.65 2840.55,3417.32
Keep-Out Layer:
  circle w15.75: c2928.82,472.44 r118.11
  circle w15.75: c857.95,472.44 r118.11
  circle w15.75: c306.77,437.01 r118.11
  circle w15.75: c306.77,2507.87 r118.11
  circle w15.75: c857.95,2472.44 r118.11
  circle w15.75: c2928.82,2472.44 r118.11
  region: 3236.22,4456.69 3212.6,4456.69 3212.6,0 3236.22,0
  rectangle: 0,0 23.62,4456.69
  rectangle: 0,0 3236.22,23.62
  region: 0,4456.69 0,4433.07 3236.22,4433.07 3236.22,4456.69
Mechanical 4:
  rectangle: 236.22,4358.27 925.2,4456.69

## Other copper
Top Layer:
  rectangle net GND: 3093.5,1773.6 3142.6,1785.4
  rectangle net GND: 2645.67,2551.18 2740.16,2692.91
  rectangle net 5V0: 2645.67,2251.97 2740.16,2393.7
  region net LX: 2768.7,1712.6 2645.67,1712.6 2645.67,1622.32 2768.7,1622.32
  rectangle net 1V2: 2850.39,2100 3027.56,2195
  rectangle net 5V0: 2824.06,1449.65 2951.2,1558.01
  rectangle net 5V0: 2881.48,1479.25 3013.03,1700.34
  rectangle net GND: 3011.8,1366.15 3031.49,1405.52
  pour cut-out: 2554.02,3195 2554.02,2865 2194.02,2865 2194.02,3195
  pour cut-out: 995.43,2007.56 2055.43,2007.56 2055.43,947.56 995.43,947.56
Bottom Layer:
  rectangle net GND: 2645.67,598.43 2740.16,696.85
  rectangle net 5V0: 2645.67,251.97 2740.16,346.46
  rectangle net GND: 2645.67,2598.43 2740.16,2696.85
  rectangle net 3V3: 2562.99,570.86 2610.24,704.72
  rectangle net 3V3: 2562.99,2570.86 2610.24,2704.72
  rectangle net 5V0: 2645.67,2248.03 2740.16,2346.46
  rectangle net 5V0: 2629.92,2248.03 2740.16,2346.46
  rectangle net 1V2: 2641.13,1901.74 2787.4,2043.82
  rectangle net 1V2: 2850.39,1972.44 3031.5,2196.85
  rectangle net LX: 2645.67,1622.05 2767.72,1712.6
  region net LX: 2455.79,1920.32 2455.79,2040.32 2305.79,2040.32 2305.79,1920.32
GND-Layer5 (plane layer: these items are gaps in the copper):
  text "GND" at 1645.67,437.01 h60
VCC (plane layer: these items are gaps in the copper):
  lines w19.68: 2624.02,0 2624.02,356.3 2787.4,519.68 2787.4,637.8 2838.58,688.98 2952.76,688.98 3055.12,791.34 3055.12,1244.09 3055.12,1287.4 3055.12,1389.76 3009.88,1435 2740,1435 2735,1440 2735,1587.6 2716.3,1606.3 2614.17,1606.3 2582.68,1574.8 2452.76,1574.8 2437.01,1590.55 2437.01,2015.75 2624.02,2202.76 2624.02,2383.86 2629.92,2389.76 2795.28,2389.76 2917.32,2267.72 3068.72,2267.72 3116,2315 3116,3975 3046,4045 2728,4045 2711.76,4061.24 2711.76,4456.69
  text "5V0" at 2791.34,1826.77 h60
  text "3V3" at 1657.48,437.01 h60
